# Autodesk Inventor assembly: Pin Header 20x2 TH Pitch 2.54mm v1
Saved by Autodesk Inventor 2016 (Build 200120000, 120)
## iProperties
Created: 2018-05
Part Number: Pin Header 20x2 TH Pitch 2.54mm v1
Document SubType Name: Assembly
Designer: Administrator
Title: Pin Header 20x2 TH Pitch 2.54mm v1
Author: Administrator
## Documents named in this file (3)
- c:\worker\convert-fusion-mar-2018\tmp\job-1\16\output\files\8c58ff39-88bb-4352-afd9-60265520bae5\Pin Header 20x2 TH Pitch 2.54mm v1.iam
- c:\worker\convert-fusion-mar-2018\tmp\job-1\16\output\files\8c58ff39-88bb-4352-afd9-60265520bae5\pins.ipt
- c:\worker\convert-fusion-mar-2018\tmp\job-1\16\output\files\8c58ff39-88bb-4352-afd9-60265520bae5\spacers.iam
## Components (2 placed, 2 different names)
1. pins:1
2. spacers:1 [sub-assembly]
